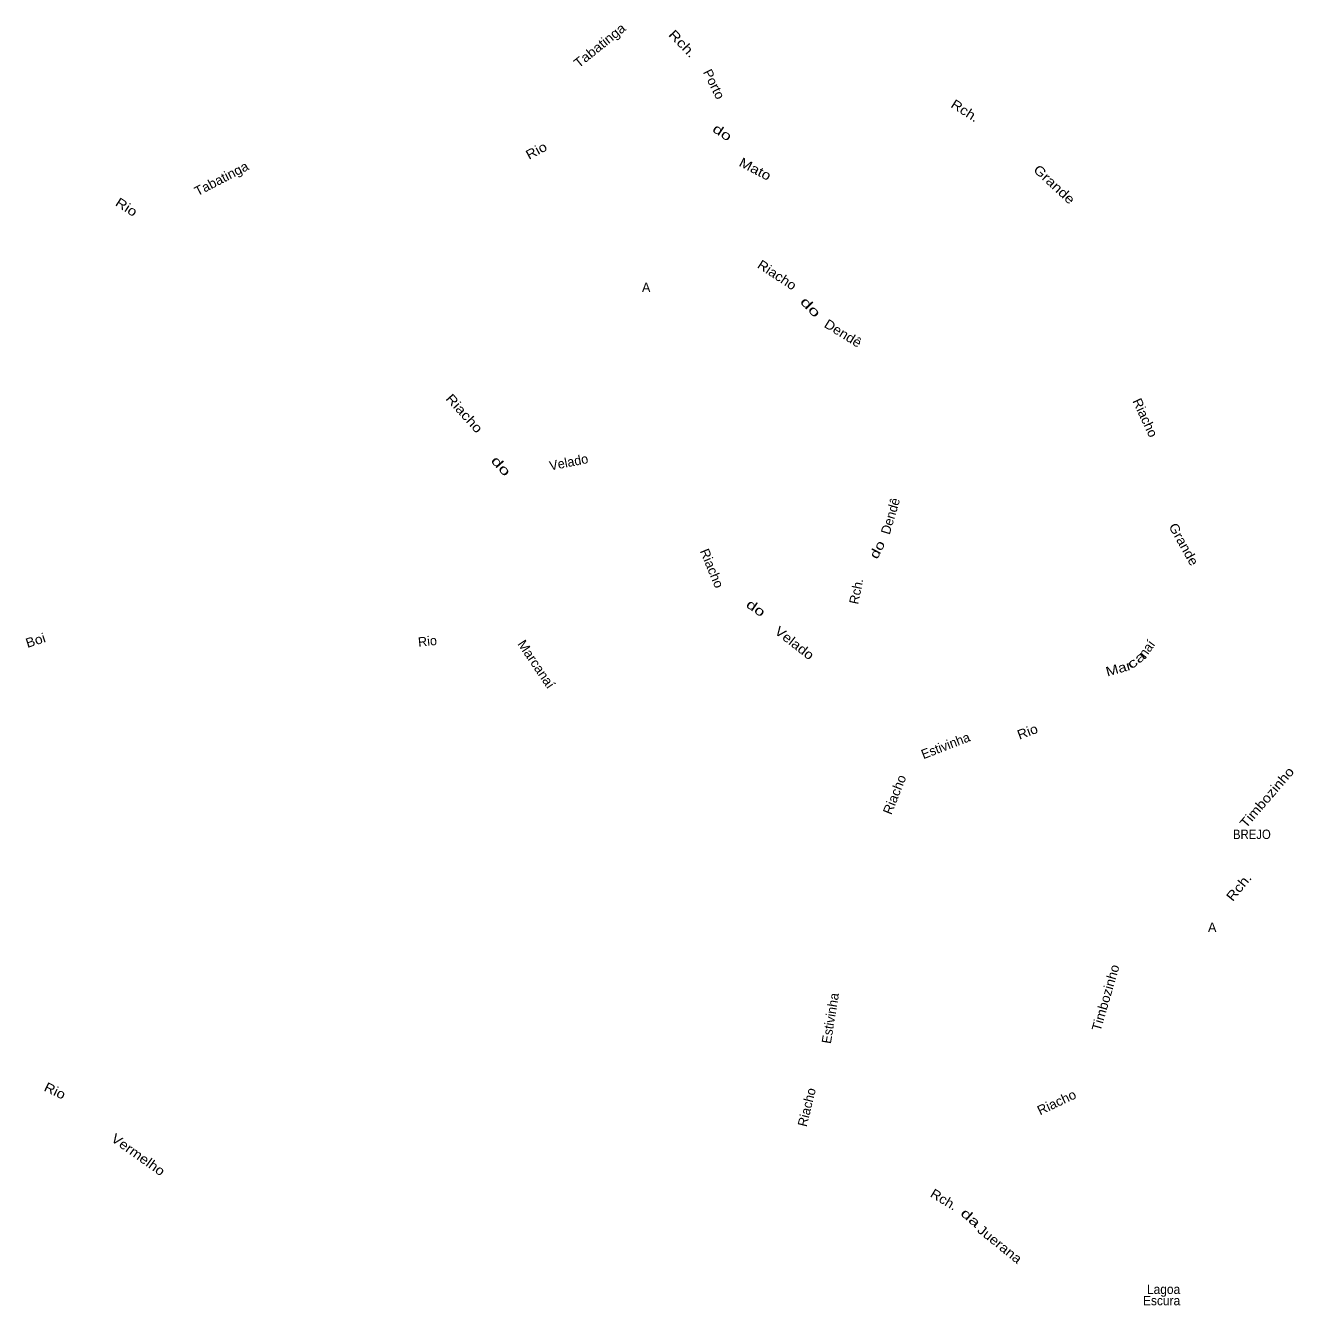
# Model space of a CAD drawing. Extents: x 649844 to 663669, y 8700676 to 8714511.
# Drawn here: x 656783 to 663511, y 8707718 to 8714511 of the extents above; entities that cross this region are included whole.
import ezdxf
from ezdxf.enums import TextEntityAlignment as Align

# ---------------------------------------------------------------- set-up
doc = ezdxf.new("R2010")
doc.units = 0
doc.header["$LTSCALE"] = 20
doc.layers.add('20', color=7, linetype='Continuous')
doc.layers.add('51', color=7, linetype='Continuous')

msp = doc.modelspace()

# ---------------------------------------------------------------- texts
at = {"layer": '20'}
msp.add_text('A', height=50, rotation=0.001, dxfattribs=at).set_placement((660054.44, 8713096.87))
at = {"layer": '20', "width": 0.9}
msp.add_text('BREJO', height=50, rotation=0.001, dxfattribs=at).set_placement((663291.05, 8710193.42), align=Align.CENTER)
at = {"layer": '20'}
msp.add_text('A', height=50, rotation=0.001, dxfattribs=at).set_placement((663080.44, 8709700.17), align=Align.CENTER)
at = {"layer": '51'}
for s, rotation, width, p in [('Tabatinga', 38.862, 1.1, (659845.62, 8714386.23)), ('Rch.', 314.106, 1.25, (660251.39, 8714397.96)), ('Porto', 296.45, 1.05, (660414.23, 8714189.34)), ('Rch.', 327.455, 1.15, (661755.49, 8714038.24)), ('do', 326.601, 1.4, (660466.95, 8713923.23)), ('Rio', 28.265, 1.15, (659505.5, 8713825.2)), ('Tabatinga', 27.543, 1.05, (657834.05, 8713676.6)), ('Mato', 332.53, 1.2, (660643.63, 8713727.57)), ('Grande', 317.23, 1.2, (662225.65, 8713649.59)), ('Rio', 327.289, 1.2, (657305.4, 8713526.7)), ('Riacho', 326.77, 1.1, (660757.73, 8713166.46)), ('do', 314.059, 1.6, (660930.97, 8712999.26)), ('Dendê', 328.267, 1.1, (661108.68, 8712856.64)), ('Riacho', 311.999, 1.2, (659093.19, 8712436.08)), ('Riacho', 295.037, 1.05, (662702.17, 8712419.21)), ('do', 312.221, 1.55, (659287.85, 8712156.66)), ('Grande', 299.146, 1.1, (662907.6, 8711745.71)), ('Riacho', 292.574, 1.05, (660402.4, 8711620.97)), ('do', 62.99, 1.3, (661324.76, 8711718.35)), ('do', 325.061, 1.4, (660644.61, 8711399.06)), ('Velado', 322.137, 1.15, (660848.31, 8711214.24)), ('Boi', 18.088, 1.1, (656843.79, 8711223.89)), ('Marcanaí', 304.035, 1.05, (659473.28, 8711107.55)), ('Mar', 15.832, 1.2, (662590.33, 8711074.58)), ('ca', 37.978, 1.45, (662692.86, 8711124.04)), ('Rio', 20.54, 1.1, (662108.89, 8710739.84)), ('Riacho', 68.279, 1.05, (661417.99, 8710420.27)), ('Timbozinho', 49.311, 1.15, (663389.48, 8710398.09)), ('Rch.', 50.642, 1.2, (663241.22, 8709922.35)), ('Timbozinho', 73.777, 1.05, (662538.4, 8709344.04)), ('Rio', 334.448, 1.15, (656928.48, 8708834.44)), ('Riacho', 25.324, 1.05, (662265.5, 8708773.24)), ('Vermelho', 324.467, 1.15, (657366.53, 8708497.73)), ('Rch.', 329.063, 1.1, (661644.2, 8708258.4)), ('da', 318.931, 1.5, (661782.49, 8708164.31)), ('Juerana', 321.157, 1.15, (661937.66, 8708023.29))]:
    msp.add_text(s, height=50, rotation=rotation, dxfattribs=dict(at, width=width)).set_placement(p, align=Align.CENTER)
for s, rotation, p in [('Velado', 11.298, (659670.43, 8712169.33)), ('Dendê', 73.407, (661396.68, 8711900.43)), ('Rio', 5.775, (658918.5, 8711218.73)), ('naí', 53.904, (662753.5, 8711188.88)), ('Estivinha', 21.229, (661674.5, 8710665.78)), ('Estivinha', 80.69, (661078.46, 8709238.11)), ('Riacho', 76.044, (660953.17, 8708763.91))]:
    msp.add_text(s, height=50, rotation=rotation, dxfattribs=at).set_placement(p, align=Align.CENTER)
msp.add_text('Rch.', height=50, rotation=78.372, dxfattribs=at).set_placement((661229.5, 8711571.01), align=Align.RIGHT)
at = {"layer": '51', "width": 0.95}
for s, p in [('Lagoa', (662910.7, 8707778.58)), ('Escura', (662910.7, 8707718.58))]:
    msp.add_text(s, height=50, dxfattribs=at).set_placement(p, align=Align.RIGHT)

doc.saveas('drawing.dxf')
